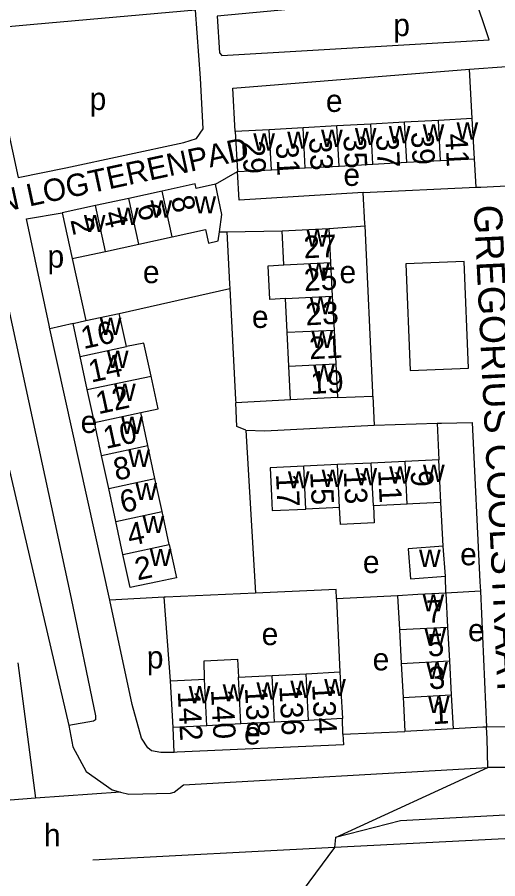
# Model space of a CAD drawing. Extents: x 159294 to 161936, y 384538 to 386517.
# Drawn here: x 160840.4 to 160926.2, y 385320 to 385473.9 of the extents above; entities that cross this region are included whole.
import ezdxf

# ---------------------------------------------------------------- set-up
doc = ezdxf.new("R2010")
doc.units = 0
for name, color, linetype in [('BLT_Basislijn', 7, 'Continuous'), ('BLT_Bebouwing', 7, 'Continuous'), ('BLT_Centroide', 7, 'Continuous'), ('BLT_Huisnummer', 7, 'Continuous'), ('BLT_Huisnummer_ tussenligend', 7, 'Continuous'), ('BLT_Onderverdeling_panden', 7, 'Continuous'), ('BLT_Straatnaam', 7, 'Continuous'), ('BLT_Straatnaam_verkleind', 7, 'Continuous'), ('BLT_Vlakafsluiter', 7, 'Continuous')]:
    doc.layers.add(name, color=color, linetype=linetype)

msp = doc.modelspace()

# ---------------------------------------------------------------- linework, layer by layer
at = {"layer": 'BLT_Basislijn'}
for p, q in [((160921.11, 385464.61), (160927.72, 385465.05)), ((160921.63, 385455.76), (160921.11, 385464.61)), ((160922.29, 385443.49), (160922.02, 385448.6)), ((160875.79, 385444.04), (160879.72, 385446.3)), ((160902.17, 385442.55), (160922.29, 385443.49)), ((160876.51, 385435.52), (160877.8, 385435.54)), ((160877.8, 385435.54), (160887.68, 385435.69)), ((160896.04, 385436.11), (160902.49, 385436.6)), ((160850.23, 385430.76), (160852.64, 385419.68)), ((160858.64, 385420.97), (160878.37, 385425.42)), ((160850.38, 385419.19), (160846.25, 385418.24)), ((160856.94, 385369.78), (160846.25, 385418.24)), ((160897.55, 385405.93), (160903.9, 385406.18)), ((160903.9, 385406.18), (160904.12, 385400.98)), ((160889.19, 385405.51), (160879.43, 385404.98)), ((160881.23, 385400.12), (160882.94, 385371.02)), ((160904.12, 385400.98), (160915.35, 385401.36)), ((160915.35, 385401.36), (160915.66, 385394.82)), ((160916.45, 385379.38), (160916.02, 385387.18)), ((160916.88, 385371.01), (160916.85, 385374.02)), ((160923.08, 385371.35), (160916.88, 385371.01)), ((160923.08, 385371.35), (160924.17, 385347.07)), ((160866.65, 385370.28), (160856.94, 385369.78)), ((160867.79, 385355.33), (160866.65, 385370.28)), ((160908.29, 385370.55), (160897.4, 385370.01)), ((160897.4, 385370.01), (160898, 385356.94)), ((160840.55, 385358.54), (160843.69, 385334.37)), ((160898.55, 385345.81), (160898.44, 385348.61)), ((160868.42, 385342.57), (160868.24, 385347)), ((160898.55, 385345.81), (160909.6, 385346.32)), ((160927.93, 385347.12), (160924.17, 385347.07)), ((160995.87, 385335.01), (160908.8, 385330.37)), ((160908.8, 385330.37), (160897.21, 385327.37)), ((160996.17, 385330.6), (160907.54, 385326.13)), ((160897.21, 385327.37), (160897.01, 385325.57)), ((160907.54, 385326.13), (160897.01, 385325.57)), ((160897.01, 385325.57), (160853.91, 385323.31))]:
    msp.add_line(p, q, dxfattribs=at)
for points in [[(160819.24, 385512.66), (160850.07, 385370.04), (160854.37, 385349.12), (160854.37, 385348.36), (160854.05, 385348.16), (160849.62, 385347.35)], [(160809.54, 385510.1), (160809.69, 385509.41), (160810.13, 385508.87), (160812.06, 385507.69), (160812.49, 385507.06), (160849.62, 385347.35)], [(160900.28, 385476.34), (160876.08, 385474.03), (160876.54, 385467.53), (160876.91, 385467.05), (160924.61, 385469.82), (160921.89, 385478.04), (160921.57, 385478.31), (160900.28, 385476.34)], [(160873.12, 385462.95), (160872.23, 385475.13), (160843.41, 385472.58)], [(160843.41, 385472.58), (160834.81, 385471.81), (160840.62, 385445.22), (160849.1, 385446.98)], [(160879.33, 385453.46), (160878.91, 385461.22), (160921.11, 385464.61)], [(160849.1, 385446.98), (160870.17, 385451.48), (160872.44, 385452.19), (160873.61, 385453.95), (160873.12, 385462.95)], [(160902.17, 385442.55), (160880, 385441.2), (160879.72, 385446.3)], [(160922.29, 385443.49), (160923.17, 385443.53), (160928.87, 385443.8)], [(160902.49, 385436.6), (160902.48, 385436.96), (160902.17, 385442.55)], [(160846.25, 385418.24), (160846.12, 385418.86), (160842.08, 385437.86), (160848.45, 385438.92)], [(160877.8, 385435.54), (160878.33, 385426.22), (160878.37, 385425.42)], [(160903.9, 385406.18), (160903.88, 385406.82), (160902.49, 385436.6)], [(160909.76, 385429.84), (160910.53, 385410.77), (160920.96, 385411.2), (160920.19, 385430.26), (160909.76, 385429.84)], [(160878.37, 385425.42), (160879.4, 385405.57), (160879.43, 385404.98)], [(160881.23, 385400.12), (160879.64, 385400.76), (160879.43, 385404.98)], [(160915.35, 385401.36), (160916.11, 385401.38), (160921.62, 385401.46), (160923, 385373), (160923.08, 385371.35)], [(160881.23, 385400.12), (160884.62, 385400.02), (160904.12, 385400.98)], [(160882.94, 385371.02), (160866.86, 385370.29), (160866.65, 385370.28)], [(160897.4, 385370.01), (160897.32, 385371.68), (160882.94, 385371.02)], [(160868.42, 385342.57), (160866.04, 385342.54), (160864.41, 385342.83), (160863.71, 385343.37), (160862.6, 385345.08), (160860.96, 385351.1), (160856.94, 385369.78)], [(160849.62, 385347.35), (160850.35, 385343.56), (160852.74, 385339.16), (160857.35, 385335.86), (160858.86, 385335.49)], [(160924.17, 385347.07), (160923.51, 385347.06), (160918.19, 385346.79)], [(160924.4, 385339.84), (160924.26, 385345.05), (160924.17, 385347.07)], [(160898.55, 385345.81), (160898.62, 385343.89), (160868.98, 385342.58), (160868.42, 385342.57)], [(160858.86, 385335.49), (160860.37, 385335.12), (160867.78, 385335.31), (160868.45, 385335.44), (160870.07, 385336.79), (160924.4, 385339.84)]]:
    msp.add_lwpolyline(points, dxfattribs=at)
at = {"layer": 'BLT_Bebouwing'}
for p, q in [((160915.59, 385455.43), (160909.55, 385455.1)), ((160921.63, 385455.76), (160915.59, 385455.43)), ((160922.02, 385448.6), (160921.63, 385455.76)), ((160885.38, 385453.78), (160879.33, 385453.46)), ((160891.42, 385454.11), (160885.38, 385453.78)), ((160897.46, 385454.44), (160891.42, 385454.11)), ((160903.51, 385454.77), (160897.46, 385454.44)), ((160909.55, 385455.1), (160903.51, 385454.77)), ((160879.33, 385453.46), (160879.72, 385446.3)), ((160897.85, 385447.29), (160903.89, 385447.62)), ((160903.89, 385447.62), (160909.94, 385447.95)), ((160909.94, 385447.95), (160915.98, 385448.28)), ((160915.98, 385448.28), (160922.02, 385448.6)), ((160879.72, 385446.3), (160885.77, 385446.63)), ((160885.77, 385446.63), (160891.81, 385446.96)), ((160891.81, 385446.96), (160897.85, 385447.29)), ((160860.34, 385441.51), (160854.4, 385440.22)), ((160866.28, 385442.8), (160860.34, 385441.51)), ((160854.4, 385440.22), (160848.45, 385438.92)), ((160848.45, 385438.92), (160850.23, 385430.76)), ((160887.68, 385435.69), (160896.04, 385436.11)), ((160887.98, 385429.66), (160887.68, 385435.69)), ((160896.04, 385436.11), (160896.34, 385430.08)), ((160862.12, 385433.35), (160868.06, 385434.64)), ((160856.17, 385432.05), (160862.12, 385433.35)), ((160850.23, 385430.76), (160856.17, 385432.05)), ((160896.34, 385430.08), (160896.65, 385424.04)), ((160888.59, 385417.59), (160888.28, 385423.62)), ((160896.65, 385424.04), (160896.95, 385418)), ((160859.91, 385415.07), (160858.64, 385420.97)), ((160851.65, 385413.29), (160850.38, 385419.19)), ((160888.89, 385411.55), (160888.59, 385417.59)), ((160896.95, 385418), (160897.25, 385411.97)), ((160852.93, 385407.39), (160851.65, 385413.29)), ((160889.19, 385405.51), (160888.89, 385411.55)), ((160897.25, 385411.97), (160897.55, 385405.93)), ((160854.2, 385401.49), (160852.93, 385407.39)), ((160897.55, 385405.93), (160889.19, 385405.51)), ((160863.74, 385397.37), (160862.46, 385403.27)), ((160855.48, 385395.59), (160854.2, 385401.49)), ((160865.01, 385391.47), (160863.74, 385397.37)), ((160856.75, 385389.69), (160855.48, 385395.59)), ((160897.58, 385393.96), (160891.56, 385393.67)), ((160903.61, 385394.24), (160897.58, 385393.96)), ((160909.63, 385394.53), (160903.61, 385394.24)), ((160915.66, 385394.82), (160909.63, 385394.53)), ((160916.02, 385387.18), (160915.66, 385394.82)), ((160866.29, 385385.57), (160865.01, 385391.47)), ((160858.03, 385383.79), (160856.75, 385389.69)), ((160897.94, 385386.32), (160891.92, 385386.03)), ((160909.99, 385386.89), (160903.97, 385386.61)), ((160867.56, 385379.67), (160866.29, 385385.57)), ((160859.3, 385377.89), (160858.03, 385383.79)), ((160916.85, 385374.02), (160916.45, 385379.38)), ((160916.88, 385371.01), (160917.21, 385364.96)), ((160908.29, 385370.55), (160908.62, 385364.49)), ((160908.62, 385364.49), (160908.95, 385358.44)), ((160917.21, 385364.96), (160917.54, 385358.9)), ((160908.95, 385358.44), (160909.27, 385352.38)), ((160917.54, 385358.9), (160917.86, 385352.85)), ((160891.96, 385356.62), (160898, 385356.94)), ((160868.24, 385347), (160867.79, 385355.33)), ((160879.88, 385355.98), (160885.92, 385356.3)), ((160885.92, 385356.3), (160891.96, 385356.62)), ((160917.86, 385352.85), (160918.19, 385346.79)), ((160880.32, 385347.65), (160874.28, 385347.33)), ((160886.36, 385347.97), (160880.32, 385347.65)), ((160892.4, 385348.29), (160886.36, 385347.97)), ((160898.44, 385348.61), (160892.4, 385348.29)), ((160874.28, 385347.33), (160868.24, 385347)), ((160918.19, 385346.79), (160909.6, 385346.32))]:
    msp.add_line(p, q, dxfattribs=at)
for points in [[(160875.79, 385444.04), (160872.34, 385443.29), (160872.17, 385444.08), (160866.28, 385442.8)], [(160876.51, 385435.52), (160876.96, 385438.65), (160875.79, 385444.04)], [(160868.06, 385434.64), (160874, 385435.93), (160874.53, 385433.52), (160876.28, 385433.91), (160876.51, 385435.52)], [(160888.28, 385423.62), (160885.51, 385423.46), (160885.21, 385429.45), (160887.98, 385429.66)], [(160852.64, 385419.68), (160858.64, 385420.97)], [(160850.38, 385419.19), (160852.64, 385419.68)], [(160864.3, 385409.77), (160863.02, 385415.63), (160859.91, 385415.07)], [(160862.46, 385403.27), (160865.57, 385403.9), (160864.3, 385409.77)], [(160891.56, 385393.67), (160885.53, 385393.39), (160885.77, 385388.39), (160885.89, 385385.75), (160891.92, 385386.03)], [(160903.97, 385386.61), (160904.1, 385383.57), (160898.1, 385383.28), (160897.94, 385386.32)], [(160916.02, 385387.18), (160911.02, 385386.94), (160909.99, 385386.89)], [(160867.56, 385379.67), (160868.83, 385373.77), (160865.46, 385373.04), (160860.57, 385371.99), (160859.3, 385377.89)], [(160916.45, 385379.38), (160910.21, 385378.92), (160910.61, 385373.56), (160916.85, 385374.02)], [(160916.88, 385371.01), (160911.89, 385370.74), (160908.29, 385370.55)], [(160873.83, 385355.66), (160873.81, 385358.91), (160879.72, 385359.23), (160879.88, 385355.98)], [(160898, 385356.94), (160898.18, 385353.61), (160898.44, 385348.61)], [(160867.79, 385355.33), (160872.79, 385355.6), (160873.83, 385355.66)], [(160909.27, 385352.38), (160909.33, 385351.32), (160909.6, 385346.32)]]:
    msp.add_lwpolyline(points, dxfattribs=at)
at = {"layer": 'BLT_Onderverdeling_panden'}
for p, q in [((160915.98, 385448.28), (160915.59, 385455.43)), ((160885.77, 385446.63), (160885.38, 385453.78)), ((160891.81, 385446.96), (160891.42, 385454.11)), ((160897.85, 385447.29), (160897.46, 385454.44)), ((160903.89, 385447.62), (160903.51, 385454.77)), ((160909.94, 385447.95), (160909.55, 385455.1)), ((160862.12, 385433.35), (160860.34, 385441.51)), ((160868.06, 385434.64), (160866.28, 385442.8)), ((160856.17, 385432.05), (160854.4, 385440.22)), ((160887.98, 385429.66), (160896.34, 385430.08)), ((160888.28, 385423.62), (160896.65, 385424.04)), ((160888.59, 385417.59), (160896.95, 385418)), ((160851.65, 385413.29), (160859.91, 385415.07)), ((160888.89, 385411.55), (160897.25, 385411.97)), ((160852.93, 385407.39), (160864.3, 385409.77)), ((160854.2, 385401.49), (160862.46, 385403.27)), ((160855.48, 385395.59), (160863.74, 385397.37)), ((160897.94, 385386.32), (160897.58, 385393.96)), ((160903.97, 385386.61), (160903.61, 385394.24)), ((160909.99, 385386.89), (160909.63, 385394.53)), ((160891.92, 385386.03), (160891.56, 385393.67)), ((160856.75, 385389.69), (160865.01, 385391.47)), ((160858.03, 385383.79), (160866.29, 385385.57)), ((160859.3, 385377.89), (160867.56, 385379.67)), ((160908.62, 385364.49), (160917.21, 385364.96)), ((160908.95, 385358.44), (160917.54, 385358.9)), ((160874.28, 385347.33), (160873.83, 385355.66)), ((160880.32, 385347.65), (160879.88, 385355.98)), ((160886.36, 385347.97), (160885.92, 385356.3)), ((160892.4, 385348.29), (160891.96, 385356.62)), ((160909.27, 385352.38), (160917.86, 385352.85))]:
    msp.add_line(p, q, dxfattribs=at)
at = {"layer": 'BLT_Vlakafsluiter'}
for p, q in [((160930.27, 385339.9), (160924.4, 385339.84)), ((160897.21, 385327.37), (160924.4, 385339.84)), ((160858.86, 385335.49), (160843.69, 385334.37)), ((160843.69, 385334.37), (160826.93, 385333.14)), ((160897.01, 385325.57), (160888.82, 385314.48))]:
    msp.add_line(p, q, dxfattribs=at)

# ---------------------------------------------------------------- texts
at = {"layer": 'BLT_Centroide'}
for s, p in [('p', (160907.52, 385470.5)), ('p', (160853.34, 385457.3)), ('e', (160895.5, 385456.95)), ('w', (160894.64, 385450.7)), ('w', (160900.67, 385451.03)), ('w', (160906.72, 385451.36)), ('w', (160912.77, 385451.69)), ('w', (160918.81, 385452.02)), ('w', (160882.55, 385450.05)), ('w', (160888.59, 385450.38)), ('e', (160898.63, 385443.74)), ('w', (160872.04, 385438.81)), ('w', (160864.2, 385438.08)), ('w', (160852.31, 385435.48)), ('w', (160858.25, 385436.78)), ('w', (160892.02, 385432.88)), ('p', (160845.83, 385429.15)), ('e', (160862.85, 385426.37)), ('w', (160892.31, 385426.84)), ('e', (160897.93, 385426.37)), ('w', (160892.62, 385420.81)), ('e', (160882.3, 385418.37)), ('w', (160855.15, 385417.12)), ('w', (160892.91, 385414.78)), ('w', (160856.42, 385411.22)), ('w', (160893.22, 385408.75)), ('w', (160857.7, 385405.34)), ('e', (160851.74, 385399.61)), ('w', (160858.97, 385399.44)), ('w', (160860.24, 385393.53)), ('w', (160912.83, 385390.86)), ('w', (160888.72, 385389.7)), ('w', (160894.75, 385389.98)), ('w', (160900.78, 385390.28)), ('w', (160906.8, 385390.58)), ('w', (160861.52, 385387.62)), ('w', (160862.79, 385381.72)), ('w', (160864.07, 385375.84)), ('w', (160912.12, 385375.69)), ('e', (160919.46, 385375.98)), ('e', (160902.1, 385374.59)), ('w', (160912.75, 385367.75)), ('e', (160884.04, 385361.73)), ('w', (160913.08, 385361.69)), ('e', (160920.86, 385362.42)), ('p', (160863.55, 385357.56)), ('e', (160903.84, 385357.21)), ('w', (160913.41, 385355.66)), ('w', (160889.16, 385352.3)), ('w', (160895.2, 385352.61)), ('w', (160871.03, 385351.33)), ('w', (160877.08, 385351.66)), ('w', (160883.12, 385351.98)), ('w', (160913.73, 385349.59)), ('e', (160880.91, 385344)), ('h', (160845.18, 385325.81))]:
    msp.add_text(s, height=4, dxfattribs=at).set_placement(p)
at = {"layer": 'BLT_Huisnummer'}
for s, rotation, p in [('33', 273.1124, (160892.49, 385452.35)), ('37', 273.1124, (160904.44, 385452.8)), ('41', 273.1204, (160916.78, 385452.99)), ('29', 273.1124, (160880.55, 385451.71)), ('8', 282.2729, (160867.82, 385441.59)), ('2', 282.2715, (160849.9, 385437.66)), ('27', 2.8621, (160891.6, 385430.79)), ('23', 2.8624, (160891.93, 385418.82)), ('16', 12.1908, (160852.26, 385414.58)), ('19', 2.8621, (160892.83, 385406.58)), ('10', 12.1908, (160856.24, 385396.75)), ('13', 272.7213, (160898.68, 385392.76)), ('9', 272.7213, (160910.62, 385392.87)), ('17', 272.717, (160886.59, 385392.26)), ('6', 12.1908, (160859.21, 385385.28)), ('2', 12.1908, (160861.88, 385373.26)), ('7', 3.0982, (160913.54, 385365.69)), ('138', 273.0511, (160881.05, 385354.09)), ('134', 273.0511, (160893.04, 385354.67)), ('142', 273.0511, (160869.06, 385353.44)), ('1', 3.0982, (160914.58, 385347.6))]:
    msp.add_text(s, height=4, rotation=rotation, dxfattribs=at).set_placement(p)
at = {"layer": 'BLT_Huisnummer_ tussenligend'}
for s, rotation, p in [('35', 273.1124, (160898.61, 385452.68)), ('39', 273.1124, (160910.69, 385453.33)), ('31', 273.1124, (160886.56, 385451.39)), ('6', 282.2715, (160861.81, 385440.16)), ('4', 282.2715, (160855.75, 385438.88)), ('25', 2.8624, (160891.66, 385424.94)), ('21', 2.8621, (160892.6, 385412.77)), ('14', 12.1908, (160853.61, 385408.59)), ('12', 12.1908, (160854.9, 385402.94)), ('8', 12.1908, (160858.07, 385391.07)), ('15', 272.7213, (160892.7, 385392.62)), ('11', 272.7213, (160904.82, 385392.97)), ('4', 12.1908, (160860.52, 385379.38)), ('5', 3.0982, (160913.73, 385359.68)), ('3', 3.0982, (160913.93, 385353.83)), ('136', 273.0511, (160887.19, 385354.4)), ('140', 273.0511, (160874.99, 385353.76))]:
    msp.add_text(s, height=4, rotation=rotation, dxfattribs=at).set_placement(p)
at = {"layer": 'BLT_Straatnaam'}
msp.add_text('GREGORIUS COOLSTRAAT', height=4.9999, rotation=272.8079, dxfattribs=at).set_placement((160921.88, 385440.24))
at = {"layer": 'BLT_Straatnaam_verkleind'}
msp.add_text('VAN LOGTERENPAD', height=4, rotation=12.1966, dxfattribs=at).set_placement((160830.35, 385437.4))

doc.saveas('drawing.dxf')
